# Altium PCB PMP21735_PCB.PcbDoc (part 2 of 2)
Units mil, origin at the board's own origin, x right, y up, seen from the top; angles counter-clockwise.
Board outline 1970 x 1570 mil, 4 copper layers (Top Layer, Signal Layer 1, Signal Layer 2, Bottom Layer), stack 61.6 mil thick; 74 components, 39 nets, 158 pads, 32 vias.
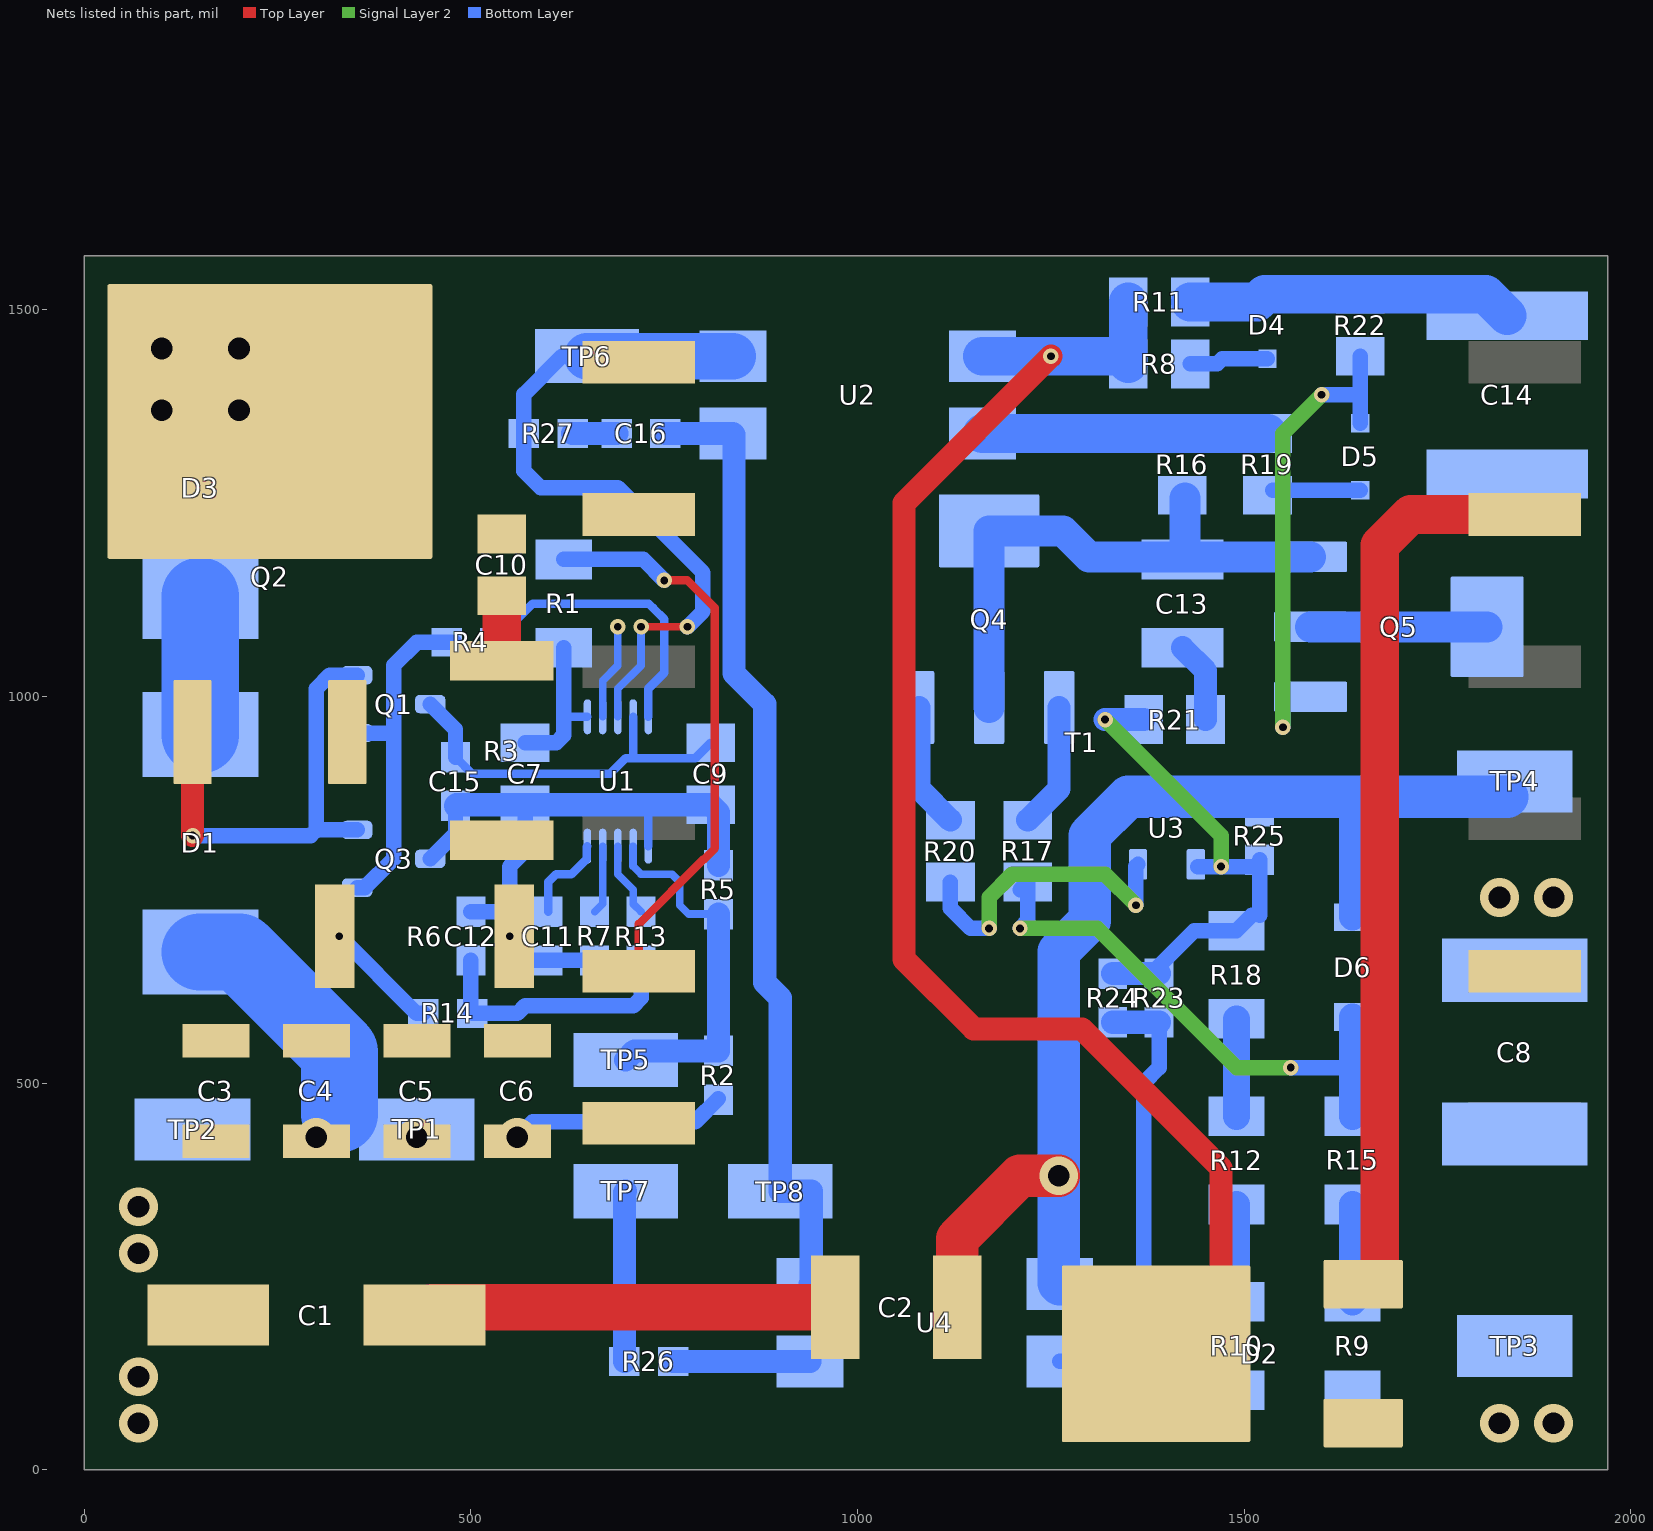
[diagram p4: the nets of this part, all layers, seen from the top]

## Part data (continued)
U2 U4: library part CMP-0006191-3, "Optocoupler, 5 kV, 80-160% CTR, SMT", Manufacturer="California Eastern Laboratories", Supplier Part Number 1=PS2501L-1-F3-H-ACT-ND, Voltage_Isolation_Vrms=5kV
U3: library part CMP-0071730-1, "Low-Voltage (1.24V) Adjustable Precision Shunt Regulators, 3-pin SOT-23, Pb-Free", Manufacturer="Texas Instruments", PackageTopMarking=RLA*XTT, PowerWise=N
ZZ1: library part CMP-0003616-3
ZZ2: library part CMP-0077236-1
ZZ3: library part CMP-0077237-1
ZZ4: library part CMP-0077238-1

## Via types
v1: diameter 50, hole 28, Top Layer to Bottom Layer, 15 vias
v2: diameter 20, hole 10, Top Layer to Bottom Layer, tented both sides, 9 vias
v3: diameter 20, hole 10, Top Layer to Bottom Layer, 7 vias
v4: diameter 50, hole 28, Top Layer to Bottom Layer, tented both sides, 1 vias

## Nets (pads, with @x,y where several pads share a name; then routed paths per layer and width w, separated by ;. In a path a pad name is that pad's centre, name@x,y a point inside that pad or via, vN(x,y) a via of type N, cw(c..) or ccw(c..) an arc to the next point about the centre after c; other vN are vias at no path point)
BASE: Q1.1 Q3.1 R4.2 | length 452
  Bottom Layer w20: Q3.1@352.76,752.6 362.6,752.6 400,790 400,950 ; Q1.1@352.76,952.6 397.4,952.6 400,950 ; R4.2@478.5,1070 430,1070 400,1040 400,950
CMP: C13.1 Q4.2 Q4.4 Q5.3 R16.2 | length 734.1
  Bottom Layer w40: Q4.2@1170,985.83 Q4.4@1170,1214.17 1265.83,1214.17 1299.45,1180.55 C13.1@1423.46,1180.55 ; R16.2@1423.46,1256.54 C13.1@1423.46,1180.55 ; Q5.3@1585.83,1180.55 C13.1@1423.46,1180.55
CMR: C13.2 R21.2 | length 105.3
  Bottom Layer w30: C13.2@1420,1062.91 1450,1032.91 R21.2@1450,970
COMP: R27.2 TP6.1 U1.3 U2.4 | length 910.6
  Top Layer w10: v3(720,1090) v3(780,1090)
  Bottom Layer w10: U1.3@690,973.66 690,1010 720,1040 v3(720,1090)
  Bottom Layer w20: TP6.1@618,1440 568.5,1390.5 R27.2@568.5,1340 568.5,1291.5 590,1270 690,1270 800,1160 800,1110 v3(780,1090)
  Bottom Layer w60: TP6.1@650,1440 U2.4@838.58,1440
CS: R13.1 U1.8 | length 97.3
  Bottom Layer w10: U1.8@690,806.34 690,770 710,750 710,731.5 R13.1@720,721.5
CSNS: C12.1 R13.2 R14.1 | length 344.4
  Bottom Layer w20: C12.1@500,658.5 500,591.5 R14.1@501.5,590 560,590 570,600 710,600 720,610 R13.2@720,658.5
CTRL: R26.2 TP7.1 | length 220.6
  Bottom Layer w30: R26.2@698.5,140 698.5,358.5 TP7.1@700,360
FBB: R18.1 R21.1 R23.2 R24.2 R25.2 U3.1 | length 652.1
  Signal Layer 2 w20: v2(1320,970) 1470,820 v2(1470,780)
  Bottom Layer w20: R23.2@1390,651.5 1435.59,697.09 R18.1@1490,697.09 R18.1@1510,717.09 ; U3.1@1440.16,780 v2(1470,780) R25.2@1511.5,780 ; R18.1@1520,717.09 R25.2@1520,788.5
  Bottom Layer w30: v2(1320,970) R21.1@1370,970 ; R24.2@1330,641.5 R23.2@1390,641.5
FBM: R12.1 R18.2 | length 125.8
  Bottom Layer w35: R12.1@1490,457.09 R18.2@1490,582.91
FBT: R10.1 R12.2 | length 125.8
  Bottom Layer w35: R10.1@1490,217.09 R12.2@1490,342.91
GATE: Q1.2 Q2.1 Q3.2 | length 592.3
  Top Layer w30: v3(140,820) Q2.1@140,953.94
  Bottom Layer w20: v3(140,820) 292.6,820 300,827.4 ; Q3.2@352.76,827.4 300,827.4 ; Q1.2@352.76,1027.4 317.4,1027.4 300,1010 300,827.4
GND: C1.2 C3.2 C4.2 C5.2 C6.2 C7.2 C9.2 C11.2 C12.2 C15.2 C16.2 Q3.3 R3.1 R5.1 R6.1 R7.1 TP2.1 TP8.1 U1.2 U1.6 U2.3 U4.2 | length 2296.4
  Bottom Layer w10: U1.2@670.31,973.66 670.31,1020.31 690,1040 v3(690,1090)
  Bottom Layer w11: U1.6@729.37,806.34 729.37,859.37 730,860
  Bottom Layer w20: Q3.3@447.24,790 480,822.76 C15.2@480,858.5 ; C12.2@500,721.5 548.5,721.5 550,720 ; C7.2@570,860 570,800 550,780 550,720 ; R7.1@660,658.5 551.5,658.5 550,660 v3(550,690) 550,720
  Bottom Layer w30: C15.2@480,858.5 481.5,860 C7.2@570,860 730,860 C9.2@810,860 820,850 R5.1@820,781.5 ; C16.2@751.5,1340 U2.3@838.58,1340 840,1338.58 840,1030 880,990 880,630 900,610 TP8.1@900,360 940,360 940,241.42 U4.2@938.58,240
  other v1: 70,60 70,120 70,280 70,340
IGND: C2.1 C8.2 C14.2 D6.2 Q5.2 Q5.4 R25.1 T1.8 TP4.1 U3.3 U4.3 | length 1795.4
  Top Layer w55: C2.1@1128.74,210 1128.74,298.74 1210,380 v4(1260,380)
  Bottom Layer w35: D6.2@1640,714.47 1640,870
  Bottom Layer w40: Q5.2@1585.83,1090 Q5.4@1814.17,1090
  Bottom Layer w55: U4.3@1261.42,240 1260,241.42 v4(1260,380) 1260,670 1300,710 1300,820 1350,870 1640,870 TP4.1@1840,870
  other v1: 1830,740 1900,740
NetC16_1: C16.1 R27.1 | length 57
  Bottom Layer w30: R27.1@631.5,1340 C16.1@688.5,1340
OUT: R4.1 U1.5 | length 383.3
  Bottom Layer w11: R4.1@531.5,1070 531.5,1071.5 580,1120 729.8,1120 735.3,1114.5 735.5,1114.5 750,1100 750,1030.63 729.37,1010 U1.5@729.37,973.66
RBT: R9.1 R15.2 | length 125.8
  Bottom Layer w35: R9.1@1640,217.09 R15.2@1640,342.91
RSNS: Q2.3 R6.2 R14.2 | length 150.2
  Bottom Layer w20: v3(329.76,690) 429.76,590 R14.2@438.5,590
RT: R7.2 U1.9 | length 89.1
  Bottom Layer w10: R7.2@660,721.5 670.31,731.81 U1.9@670.31,806.34
SECSS: C14.1 D4.2 R11.1 R22.1 | length 425.6
  Bottom Layer w50: R11.1@1430,1510 1516.69,1510 1526.69,1520 R22.1@1650,1520 1812.36,1520 C14.1@1840,1492.36
SNB: C10.2 R3.2 | length 78
  Top Layer w50: C10.2@540,1120 540,1056.14 R3.2@550,1046.14
SS: C11.1 U1.10 | length 117.5
  Bottom Layer w11: C11.1@600,721.5 600,760 610,770 630,770 650,790 650,805.71 U1.10@650.63,806.34
SWP: C10.1 D3.2 Q2.4 T1.1 T1.2
  other v1: 100,1370 200,1370 100,1450 200,1450
SWS: D2.3 T1.11 | length 1168.5
  Top Layer w50: D2.3@1653.86,239.76 1675.43,261.34 1675.43,1195.43 1715.28,1235.28 T1.11@1862.83,1235.28
SWZ: D1.1 D3.1 | length 179
  Bottom Layer w100: D1.1@150,950.49 D3.1@150,1129.51
UVLO: R2.1 R5.2 TP5.1 U1.7 | length 481.3
  Bottom Layer w10: U1.7@709.68,806.34 709.68,780.32 720,770 760,770 770,760 770,730 781.5,718.5 R5.2@820,718.5
  Bottom Layer w30: TP5.1@700,530 711.5,541.5 R2.1@820,541.5 R5.2@820,718.5
VBN: Q4.1 R17.2 | length 162.6
  Bottom Layer w30: R17.2@1220,840 1260.55,880.55 Q4.1@1260.55,985.83
VBP: D5.1 Q5.1 R22.2 | length 627.4
  Signal Layer 2 w20: v2(1550,960) 1550,1340 v2(1600,1390)
  Bottom Layer w20: v2(1550,960) Q5.1@1550,1000 ; v2(1600,1390) 1650,1390 ; D5.1@1650,1353.31 1650,1390 ; R22.2@1650,1440 1650,1390
VBZ: D6.1 R15.1 R17.1 | length 711.8
  Signal Layer 2 w20: v2(1210,700) 1310,700 1490,520 v2(1560,520)
  Bottom Layer w20: v2(1210,700) 1220,710 R17.1@1220,760 R17.1@1210,750 ; v2(1560,520) 1638.69,520 1640,521.31
  Bottom Layer w35: R15.1@1640,457.09 1640,521.31 D6.1@1640,585.53
VC: R23.1 R24.1 U4.4 | length 591.9
  Bottom Layer w20: U4.4@1261.42,140 1330,140 1370,180 1370,500 1390,520 R23.1@1390,578.5
  Bottom Layer w30: R24.1@1330,578.5 R23.1@1390,578.5
VCC: C9.1 C15.1 Q1.3 U1.4 | length 491.3
  Bottom Layer w11: C15.1@480,921.5 501.5,900 680,900 700,920 710,920 ; U1.4@709.68,973.66 709.68,920.32 710,920 ; C9.1@810,940 790,920 710,920
  Bottom Layer w20: Q1.3@447.24,990 480,957.24 C15.1@480,921.5
VD: R26.1 U4.1 | length 177.1
  Bottom Layer w30: R26.1@761.5,140 U4.1@938.58,140
VDA: D5.2 R19.1 | length 113.3
  Bottom Layer w20: R19.1@1536.69,1266.69 D5.2@1650,1266.69
VDK: D4.1 R8.2 | length 102.8
  Bottom Layer w20: R8.2@1430,1430 1465,1430 1471.69,1436.69 D4.1@1530,1436.69
VEK: R20.1 U3.2 | length 407.6
  Signal Layer 2 w20: v2(1170,700) 1170,740 1200,770 1320,770 v2(1360,730)
  Bottom Layer w20: R20.1@1120,760 1120,726 1146,700 v2(1170,700) ; v2(1360,730) 1360,780.16 U3.2@1362.6,782.76
VEN: Q4.3 R20.2 | length 162.6
  Bottom Layer w30: Q4.3@1079.45,985.83 1079.45,880.55 R20.2@1120,840
VIN: C1.1 C2.2 C3.1 C4.1 C5.1 C6.1 D1.2 R1.2 R2.2 T1.5 T1.6 TP1.1 | length 1862.4
  Top Layer w11: T1.5@717.17,644.72 717.17,705.87 799.81,788.52 800.56,788.52 815.5,803.45 815.5,1114.5 780,1150 v3(750,1150)
  Top Layer w60: C1.1@439.76,200 449.76,210 C2.2@971.26,210
  Bottom Layer w20: v1(560,430) 580,450 790,450 R2.2@820,480 ; R1.2@620,1177.09 722.91,1177.09 v3(750,1150)
  Bottom Layer w100: D1.2@150,669.51 200.49,669.51 330,540 330,460
  other v1: 300,430 430,430
VINR: C7.1 R1.1 U1.1 | length 200.3
  Bottom Layer w11: 620,980 626.34,973.66 U1.1@650.63,973.66
  Bottom Layer w20: C7.1@570,940 610,940 620,950 620,980 R1.1@620,1062.91
VK: R16.1 R19.2 U2.2 | length 368.6
  Bottom Layer w50: U2.2@1161.42,1340 R19.2@1530,1340
VOUT: C8.1 D2.1 D2.4 R8.1 R9.2 R10.2 R11.2 TP3.1 U2.1 | length 1928
  Top Layer w30: v2(1250,1440) 1060,1250 1060,660 1150,570 1290,570 1470,390 1470,233.86 D2.4@1386.14,150
  Bottom Layer w50: U2.1@1161.42,1440 v2(1250,1440) 1340,1440 R8.1@1350,1430 R11.2@1350,1510
  other v1: 1830,60 1900,60
pads on no net: LBL1.0 T1.3 T1.4 T1.7 T1.9 T1.10 T1.12

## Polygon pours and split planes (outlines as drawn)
GND on Bottom Layer "BOTTOM_LAYER_GND_P000" (solid, remove dead copper, pour order 0): 900,0 980,0 980,405 900,485 900,1570 0,1570 0,0
IGND on Signal Layer 2 "SIGNAL_LAYER_2_IGND_P022" (solid, remove dead copper, pour order 22): 1100,0 1100,600 1038.11,661.89 1038.11,1568.11 1040,1570 1970,1570 1970,0
GND on Signal Layer 2 "SIGNAL_LAYER_2_GND_P008" (solid, remove dead copper, pour order 8): 900,0 980,0 980,405 900,485 900,1570 0,1570 0,0
GND on Top Layer "TOP_LAYER_GND_P012" (solid, remove dead copper, pour order 12): 900,0 980,0 980,405 900,485 900,1570 0,1570 0,0
IGND on Signal Layer 1 "SIGNAL_LAYER_1_IGND_P020" (solid, remove dead copper, pour order 20): 1100,0 1100,600 1038.11,661.89 1038.11,1568.11 1040,1570 1970,1570 1970,0
GND on Signal Layer 1 "SIGNAL_LAYER_1_GND_P014" (solid, remove dead copper, pour order 14): 900,0 980,0 980,405 900,485 900,1570 0,1570 0,0

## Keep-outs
Keep-Out Layer:
  text ".Layer_Name" at 577,-858.49 h60

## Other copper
Top Layer:
  rectangle net RSNS: 250,622.48 420,1020
  rectangle net VIN: 640,470 790,675.9
  rectangle net VIN: 130,360 350,480
  rectangle net VIN: 320,30 790,480
  rectangle net GND: 90,30 290,340
  rectangle net GND: 30,30 100,590
  rectangle net GND: 30,500 480,590
  rectangle net GND: 450,500 610,840
  rectangle net SWP: 40,1200 800,1530
  rectangle net IGND: 1790,620 1940,770
  rectangle net VOUT: 1270,30 1940,90
  text ".Layer_Name" at 577,-858.49 h60
Bottom Layer:
  rectangle net GND: 729.37,800 812.05,859.37
  rectangle net SWP: 30,1230 450,1530
  rectangle net VIN: 280,320 590,490
  rectangle net VIN: 280,30 520,490
  rectangle net GND: 30,30 250,490
  rectangle net VOUT: 1450,40 1770,130
  rectangle net VOUT: 1760,40 1940,480
  rectangle net IGND: 1760,600 1940,1350
  text ".Layer_Name" at 577,-858.49 h60

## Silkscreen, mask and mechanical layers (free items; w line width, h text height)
Top Overlay:
  text ".Layer_Name" at 577,-858.49 h60
Bottom Overlay:
  region: 830,100 530,100 530,0 830,0
  text "'.PRJ_Number'.PCB_Rev-" at 1420,20 h108.27
  text ".Layer_Name" at 577,-858.49 h60
Top Paste:
  text ".Layer_Name" at 577,-858.49 h60
Bottom Paste:
  text ".Layer_Name" at 577,-858.49 h60
Top Solder:
  text ".Layer_Name" at 577,-858.49 h60
  text ".Layer_Name" at 577,-858.49 h60
Bottom Solder:
  region: 240,30 240,370 40,370 40,30
  region: 500,30 500,370 300,370 300,30
  text ".Layer_Name" at 577,-858.49 h60
Drill Guide:
  text ".Layer_Name" at 577,-858.49 h60
M1 Board Outline:
  the board outline again, w10
  text ".Layer_Name" at 577,-858.49 h60
M2 Board Dimensions:
  rectangle: 0,-275 125,-150
  rectangle: 125,-400 500,-275
  lines w7: 0,-275 1000,-275 ; 125,-400 125,-150 ; 250,-400 250,-150 ; 500,-400 500,-150 ; 750,-400 750,-150 ; 0,-400 1000,-400 1000,-150 0,-150 0,-400
  text ".Layer_Name" at 577,-858.49 h60
M3 3D STEP Top:
  text ".Layer_Name" at 577,-858.49 h60
M4 3D STEP Bottom:
  text ".Layer_Name" at 577,-858.49 h60
M5 Assembly Top:
  lines w10: -292,-930.17 6308,-930.17 ; -292,-726.83 6310,-726.83 ; -292,-523.5 -292,-1133.5 3713,-1133.5 6310,-1133.5 6310,-523.5 -291.5,-523.5 -291.5,-1133.5 1284,-1133.5 ; 2173,-1133.5 2173,-523.5 ; 3440,-726.83 3440,-523.5 ; 4280,-726.83 4280,-523.5 ; 4902,-1140 4902,-937.17
  text "COMPONENTS MARKED 'DNP' SHOULD NOT BE POPULATED." at 1153.5,-318.5 h60
  text "ASSEMBLY VARIANT:" at 1153,-434 h60
  text ".VariantName" at 2189,-434 h60
  text "PCB VIEWED FROM TOP SIDE" at -228.5,-655.67 h60
  text "BOARD #:" at 2248,-655.67 h60
  text ".PRJ_Number" at 2793.5,-655.67 h60
  text "REV:" at 3638,-655.67 h60
  text ".PCB_Rev" at 3929.5,-655.67 h60
  text "SVN REV:" at 4476,-655.67 h60
  text ".VersionControl_RevNumber" at 4982,-655.67 h60
  text "TID #:" at 2248,-859 h60
  text ".TID" at 2793.5,-859 h60
  text "PLOT NAME =" at -228.5,-1064.34 h60
  text ".plot_File_Name" at 577,-1064.34 h60
  text "GENERATED    :" at 2250,-1064.34 h60
  text ".Print_Date" at 3119.5,-1064.34 h60
  text ".Print_Time" at 3848.5,-1064.34 h60
  text "TEXAS INSTRUMENTS" at 5113,-1064.34 h60
M6 Assembly Bottom:
  lines w10: -292.5,-727.33 6309.5,-727.33 ; -290.5,-930.67 6309.5,-930.67 ; 1115.5,-1140.5 1115.5,-937.67 ; 1737.5,-727.33 1737.5,-524 ; 2577.5,-727.33 2577.5,-524 ; 3844.5,-1134 3844.5,-524 ; 4733.5,-1134 6309,-1134 6309,-524 -292.5,-524 -292.5,-1134 2304.5,-1134 6309.5,-1134 6309.5,-524
  text "COMPONENTS MARKED 'DNP' SHOULD NOT BE POPULATED." at 6102,-318 h60
  text ".VariantName" at 5058,-434 h60
  text "ASSEMBLY VARIANT:" at 6097,-434 h60
  text ".VersionControl_RevNumber" at 1035.5,-656.17 h60
  text "SVN REV:" at 1541.5,-656.17 h60
  text ".PCB_Rev" at 2088,-656.17 h60
  text "REV:" at 2379.5,-656.17 h60
  text ".PRJ_Number" at 3224,-656.17 h60
  text "BOARD #:" at 3769.5,-656.17 h60
  text "PCB VIEWED FROM BOTTOM SIDE" at 6246,-656.17 h60
  text ".TID" at 3224,-859.5 h60
  text "TID #:" at 3769.5,-859.5 h60
  text "TEXAS INSTRUMENTS" at 904.5,-1064.84 h60
  text ".Print_Time" at 2169,-1064.84 h60
  text ".Print_Date" at 2898,-1064.84 h60
  text "GENERATED    :" at 3767.5,-1064.84 h60
  text ".plot_File_Name" at 5440.5,-1064.84 h60
  text "PLOT NAME =" at 6246,-1064.84 h60
M9 Title Sheet:
  drawing of 57 lines, arcs and shapes, not listed
  text "1" at 739.84,8036.5 h70
  text "2" at 3235.5,8036.5 h70
  text "3" at 5724.84,8036.5 h70
  text "4" at 8231.51,8036.5 h70
  text "5" at 10730.5,8036.5 h70
  text "6" at 13235.5,8036.5 h70
  text "A" at -416.5,6893.5 h70
  text "A" at 14383.5,6893.5 h70
  text "B" at -416.5,4513.5 h70
  text "B" at 14383.5,4513.5 h70
  text "C" at -416.5,2138.5 h70
  text "C" at 14383.5,2138.5 h70
  text "PROJECT TITLE:" at 11343.5,277.5 h45
  text ".PRJ_Title" at 11393.5,144.17 h70
  text "DESIGNED FOR:" at 11343.5,-23.5 h45
  text ".PRJ_Customer" at 11393.5,-163.5 h70
  text "D" at -416.5,-231.5 h70
  text "D" at 14383.5,-231.5 h70
  text "FILE NAME:" at 11343.5,-323.5 h45
  text ".PCB_File_Name_No_Path" at 11393.5,-443.5 h70
  text "Texas Instruments (TI) and/or its licensors do not warrant the accuracy or completeness of this specification" at 6374,-605.34 h45
  text "ENGINEER:" at 11343.5,-613.5 h45
  text "LAYOUT BY:" at 12848.5,-613.5 h45
  text "or any information contained therein. TI and/or its licensors do not warrant that this design will meet" at 6329.01,-718 h45
  text ".PRJ_Engineer" at 11393.5,-768.49 h70
  text ".PCB_Layout" at 12899,-768.49 h70
  text "the specifications, will be suitable for your application or fit for any particular purpose, or will operate in" at 6329.01,-830.67 h45
  text ".Layer_Name" at 577,-858.49 h60
  text "ALTIUM DESIGNER VERSION:" at 12848.5,-923.5 h45
  text "an implementation. TI and/or its licensors do not warrant that the design is production worthy. You should" at 6329.01,-943.33 h45
  text "completely validate and test your design implementation to confirm the system functionality for your application." at 6374,-1056 h45
  text ".print_Scale" at 11393.5,-1056.83 h70
  text ".Application_BuildNumber" at 12899,-1056.83 h70
  text "1" at 739.84,-1263.5 h70
  text "2" at 3235.5,-1263.5 h70
  text "3" at 5724.84,-1263.5 h70
  text "4" at 8231.51,-1263.5 h70
  text "5" at 10730.5,-1263.5 h70
  text "6" at 13235.5,-1263.5 h70
M10 Fab Notes:
  drawing of 189 lines, arcs and shapes, not listed
  text "DESIGN INFORMATION" at 12382.02,6356.17 h60
  text "MIN. TRACK WIDTH:" at 11737.46,6224.05 h60
  text "8" at 12833.7,6224.05 h60
  text "MIL" at 12988.46,6224.05 h60
  text "MIN. CLEARANCE:" at 11737.46,6099.92 h60
  text "0.2" at 12773.7,6099.93 h60
  text "mm" at 12988.46,6099.92 h60
  text "MIN. VIA PAD SIZE:" at 11737.46,5975.8 h60
  text "20" at 12803.71,5975.8 h60
  text "MIL" at 12988.46,5975.8 h60
  text "0.05mm (2MIL)" at 12432.46,5845.9 h60
  text "MINIMUM ANNULAR RING" at 11408.23,5837.67 h60
  text "EXTERNAL" at 13140.46,5837.67 h60
  text "PER" at 11608.23,5727.55 h60
  text "IPC-D-275 CLASS 2 LEVEL C" at 11828.23,5727.54 h60
  text "MIL, HOLES" at 13316.46,5627.07 h60
  text "+/-" at 12924,5618.48 h60
  text "+/-" at 13778,5618.48 h60
  text "REGISTRATION TOLERANCES:" at 11408.23,5617.42 h60
  text "METAL" at 12608,5617.42 h60
  text "5" at 13184.2,5617.42 h60
  text "3" at 14017.2,5617.42 h60
  text "MIL" at 14133.46,5617.42 h60
  text "HOLE SIZE TOLERANCE (UNLESS OTHERWISE SPECIFIED):" at 11408.23,5519.1 h60
  text "+/-" at 13778,5516.23 h60
  text "3" at 14017.2,5515.17 h60
  text "MIL" at 14133.46,5515.17 h60
  text "MATERIAL:" at 11333.46,5377.52 h60
  text "FR-4 High Tg" at 12319.9,5249 h60
  text "X" at 12175.46,5241.01 h60
  text "FR-408" at 11754.46,5236.49 h60
  text "OTHER" at 13242.46,5236.49 h60
  text "62 MIL (1.6mm) +/-10%" at 12074.56,5093.46 h60
  text "X" at 11954.46,5091.01 h60
  text "THICKNESS:" at 11408.23,5085.24 h60
  text "OTHER" at 13359.46,5085.24 h60
  text "TOLERANCE:" at 11408.23,4946.92 h60
  text "X" at 12256.46,4946.92 h60
  text "ANSI IPC-6012 TYPE 3 CLASS 2" at 12434.48,4946.92 h60
  text "OTHER +/-" at 12434.46,4802.73 h60
  text "BOW & TWIST:" at 11408.23,4657.54 h60
  text "X" at 12256.46,4657.54 h60
  text "ANSI IPC-6012 TYPE 3 CLASS 2" at 12434.48,4657.54 h60
  text "OTHER +/-" at 12434.46,4510.85 h60
  text "DRILLING:" at 11333.46,4380.23 h60
  text "NC_DRILL FILES" at 13094.46,4275.04 h60
  text "REFERENCE:" at 11408.23,4271.1 h60
  text "X" at 12065.46,4271.01 h60
  text "AS SHOWN" at 12243.46,4271.1 h60
  text "X" at 12966.46,4271.1 h60
  text "OTHER" at 13392.46,4128.85 h60
  text "PTH COPPER THICKNESS:" at 11407.91,4125.32 h60
  text "X" at 12547.14,4125.32 h60
  text "20-30 um" at 12675.14,4125.32 h60
  text "BOARD FINISH:" at 11333.46,3977.73 h60
  text "SILKSCREEN:" at 11488.68,3867.6 h60
  text "X" at 12446.46,3867.6 h60
  text "TOP" at 12563.46,3867.6 h60
  text "X" at 12956.46,3867.6 h60
  text "BOTTOM" at 13074.46,3867.6 h60
  text "SILKSCREEN COLOR:" at 11488.68,3712.41 h60
  text "X" at 12445.46,3712.41 h60
  text "WHITE" at 12563.46,3712.41 h60
  text "OTHER" at 13074.46,3712.41 h60
  text "X" at 12576.46,3568.96 h60
  text "GREEN" at 12694.46,3568.96 h60
  text "OTHER" at 13312.46,3568.96 h60
  text "SOLDER RESIST COLOR:" at 11488.68,3562.1 h60
  text "X" at 12576.46,3414.71 h60
  text "MATTE" at 12694.46,3414.71 h60
  text "SEMI-GLOSS" at 13312,3414.07 h60
  text "IMMERSION GOLD (ENIG)" at 12394.46,3241.94 h60
  text "ENEPIG" at 13732,3234.72 h60
  text "SURFACE FINISH:" at 11333.46,3233.72 h60
  text "X" at 12216.46,3233.72 h60
  text "IMM. TIN/SILVER OR EQUIV" at 11663,3096.4 h60
  text "OTHER" at 13094.46,3092.47 h60
  text "ARRAY/PANEL:" at 11333.46,2937.09 h60
  text "X" at 12220,2930 h60
  text "CUT AND TRIM PER M1 BOARD OUTLINE" at 12394.46,2928.87 h60
  text "N.C. ROUTE" at 12394.46,2792.9 h60
  text "V. SCORE" at 13260.46,2792.9 h60
  text "CERTIFICATION:" at 11333.46,2663.77 h60
  text "MATERIALS AND WORKMANSHIP FOR ALL PCBS" at 12058.46,2663.77 h60
  text "TO MEET OR EXCEED THE REQUIREMENTS OF:" at 12058.46,2569.71 h60
  text "X" at 11695.97,2441.08 h60
  text "ANSI IPC-A-600F CLASS ->" at 11823.96,2441.08 h60
  text "X" at 13471.97,2441.08 h60
  text "2" at 13581.96,2441.08 h60
  text "1" at 13266.96,2439.58 h60
  text "3" at 13935.96,2439.58 h60
  text "X" at 12507.97,2293.39 h60
  text "RoHS" at 12635.96,2293.39 h60
  text "OTHER" at 13280.36,2293.39 h60
  text "PER ORDER" at 13677.42,2293.39 h60
  text "ALL BOARDS MUST MEET OR EXCEED UL94-V0 REQUIREMENTS." at 11361,2139.57 h60
  text "PCB MUST BEAR THE UL94V-0 UL REGISTERED MATERIAL ID NUMBER" at 11361,2023.5 h60
  text "ADDITIONAL REQUIREMENTS:" at 11333.46,1854.08 h60
  text "MICROSECTION:" at 11408.23,1746.95 h60
  text "YES" at 12313.96,1746.95 h60
  text "REQUIRED" at 13175.46,1602.62 h60
  text "BARE BOARD ELEC. TEST:" at 11408.23,1599.76 h60
  text "NONE" at 12713.96,1599.76 h60
  text "X" at 13650,1600 h60
  text "PER ORDER" at 13767.46,1599.76 h60
  text "XX MIL VIAS REQUIRE NON-CONDUCTIVE FILL AND PLANARIZE" at 11576.38,1394.82 h59
  text "XX MIL VIAS REQUIRE CONDUCTIVE FILL AND PLANARIZE" at 11584.38,1290.84 h60
  text "OUTER XX MIL TRACES REQUIRE 50 OHM SINGLE-ENDED IMPEDANCE" at 11583.39,1127.46 h58
  text "LAYER 2 & 3 (INNER LAYERS) XX MIL WIDE, XX MIL SPACE / TRACES REQUIRE 100 OHM DIFFERENTIAL IMPEDANCE" at 11575.39,891.74 h60
  text ".Layer_Name" at 577,-858.49 h60
M11 Gerber Information:
  lines w10: -292,-930.17 6308,-930.17 ; -292,-726.83 6310,-726.83 ; -292,-523.5 -292,-1133.5 3713,-1133.5 6310,-1133.5 6310,-523.5 -291.5,-523.5 -291.5,-1133.5 1284,-1133.5 ; 2173,-1133.5 2173,-523.5 ; 3440,-726.83 3440,-523.5 ; 4280,-726.83 4280,-523.5 ; 4902,-1140 4902,-937.17
  text "ALL ARTWORK VIEWED FROM TOP SIDE" at -228.5,-655.67 h60
  text "BOARD #:" at 2248,-655.67 h60
  text ".PRJ_Number" at 2793.5,-655.67 h60
  text "REV:" at 3638,-655.67 h60
  text ".PCB_Rev" at 3929.5,-655.67 h60
  text "SVN REV:" at 4476,-655.67 h60
  text ".VersionControl_RevNumber" at 4982,-655.67 h60
  text "LAYER NAME =" at -228.5,-858.49 h60
  text "TID #:" at 2248,-859 h60
  text ".TID" at 2793.5,-859 h60
  text "PLOT NAME =" at -228.5,-1064.34 h60
  text ".plot_File_Name" at 577,-1064.34 h60
  text "GENERATED    :" at 2250,-1064.34 h60
  text ".Print_Date" at 3119.5,-1064.34 h60
  text ".Print_Time" at 3848.5,-1064.34 h60
  text "TEXAS INSTRUMENTS" at 5113,-1064.34 h60
M12 Stackup:
  drawing of 295 lines, arcs and shapes, not listed
  text "Layer" at 9797.84,7830 h60
  text "Name" at 10207.76,7830 h60
  text "Material" at 11147.5,7830 h60
  text "Thickness" at 12007.26,7830 h60
  text "Constant" at 12657.1,7830 h60
  text "Board Layer Stack" at 13226.96,7830 h60
  text "1" at 9797.84,7710 h60
  text "Top Overlay" at 10207.76,7710 h60
  text "2" at 9797.84,7590 h60
  text "Top Solder" at 10207.76,7590 h60
  text "Solder Resist" at 11147.5,7590 h60
  text "0.40mil" at 12007.26,7590 h60
  text "3.5" at 12657.1,7590 h60
  text "3" at 9797.84,7470 h60
  text "Top Layer" at 10207.76,7470 h60
  text "Copper" at 11147.5,7470 h60
  text "1.40mil" at 12007.26,7470 h60
  text "4" at 9797.84,7350 h60
  text "Dielectric 1" at 10207.76,7350 h60
  text "FR-4" at 11147.5,7350 h60
  text "8.00mil" at 12007.26,7350 h60
  text "4.2" at 12657.1,7350 h60
  text "5" at 9797.84,7230 h60
  text "Signal Layer 1" at 10207.76,7230 h60
  text "Copper" at 11147.5,7230 h60
  text "1.40mil" at 12007.26,7230 h60
  text "6" at 9797.84,7110 h60
  text "Dielectric 2" at 10207.76,7110 h60
  text "FR-4" at 11147.5,7110 h60
  text "40.00mil" at 12007.26,7110 h60
  text "4.2" at 12657.1,7110 h60
  text "7" at 9797.84,6990 h60
  text "Signal Layer 2" at 10207.76,6990 h60
  text "Copper" at 11147.5,6990 h60
  text "1.40mil" at 12007.26,6990 h60
  text "8" at 9797.84,6870 h60
  text "Dielectric 3" at 10207.76,6870 h60
  text "FR-4" at 11147.5,6870 h60
  text "8.00mil" at 12007.26,6870 h60
  text "4.2" at 12657.1,6870 h60
  text "9" at 9797.84,6750 h60
  text "Bottom Layer" at 10207.76,6750 h60
  text "Copper" at 11147.5,6750 h60
  text "1.40mil" at 12007.26,6750 h60
  text "10" at 9797.84,6630 h60
  text "Bottom Solder" at 10207.76,6630 h60
  text "Solder Resist" at 11147.5,6630 h60
  text "0.40mil" at 12007.26,6630 h60
  text "3.5" at 12657.1,6630 h60
  text "11" at 9797.84,6510 h60
  text "Bottom Overlay" at 10207.76,6510 h60
  text ".Layer_Name" at 577,-858.49 h60
M13 Component Bodies Top:
  text ".Layer_Name" at 577,-858.49 h60
M14 Component Bodies Bottom:
  text ".Layer_Name" at 577,-858.49 h60
M15 Courtyards Top:
  text ".Layer_Name" at 577,-858.49 h60
M16 Courtyards Bottom:
  text ".Layer_Name" at 577,-858.49 h60
Drill Drawing:
  circle w10: c2363.72,1247.96 r27.63
  lines w10: 2336.09,1344.66 2391.34,1344.66 2391.34,1399.91 2336.09,1399.91 2336.09,1344.66
  lines w12: 2286,1183.04 5517.49,1183.04 ; 2286,1431.68 5517.49,1431.68 ; 2623.86,1058.72 2623.86,1556 ; 2955.86,1058.72 2955.86,1556 ; 3592.43,1058.72 3592.43,1556 ; 3851.57,1058.72 3851.57,1556 ; 4226.72,1058.72 4226.72,1556 ; 4951.05,1058.72 4951.05,1556 ; 2286,1058.72 5517.49,1058.72 5517.49,1556 2286,1556 2286,1058.72
  text "Symbol" at 2360.59,1468.98 h72
  text "Quantity" at 2661.16,1468.98 h72
  text "Finished Hole Size" at 2993.16,1468.98 h72
  text "Plated" at 3629.72,1468.98 h72
  text "Hole Type" at 3888.86,1468.98 h72
  text "Drill Layer Pair" at 4264.02,1468.98 h72
  text "Hole Tolerance" at 4988.35,1468.98 h72
  text "16" at 2661.16,1344.66 h60
  text "10.00mil (0.254mm)" at 2993.16,1344.66 h60
  text "PTH" at 3629.72,1344.66 h60
  text "Round" at 3888.86,1344.66 h60
  text "Top Layer - Bottom Layer" at 4264.02,1344.66 h60
  text "16" at 2661.16,1220.34 h60
  text "28.00mil (0.711mm)" at 2993.16,1220.34 h60
  text "PTH" at 3629.72,1220.34 h60
  text "Round" at 3888.86,1220.34 h60
  text "Top Layer - Bottom Layer" at 4264.02,1220.34 h60
  text "32 Total" at 2661.16,1096.02 h60
  text ".Layer_Name" at 577,-858.49 h60
Mechanical 17:
  text ".Layer_Name" at 577,-858.49 h60
Mechanical 18:
  text ".Layer_Name" at 577,-858.49 h60
Mechanical 19:
  text ".Layer_Name" at 577,-858.49 h60

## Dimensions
0,-400 to 1000,-400 on M2 Board Dimensions
0,0 to 0,1570 on M2 Board Dimensions
0,0 to 1970,0 on M2 Board Dimensions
